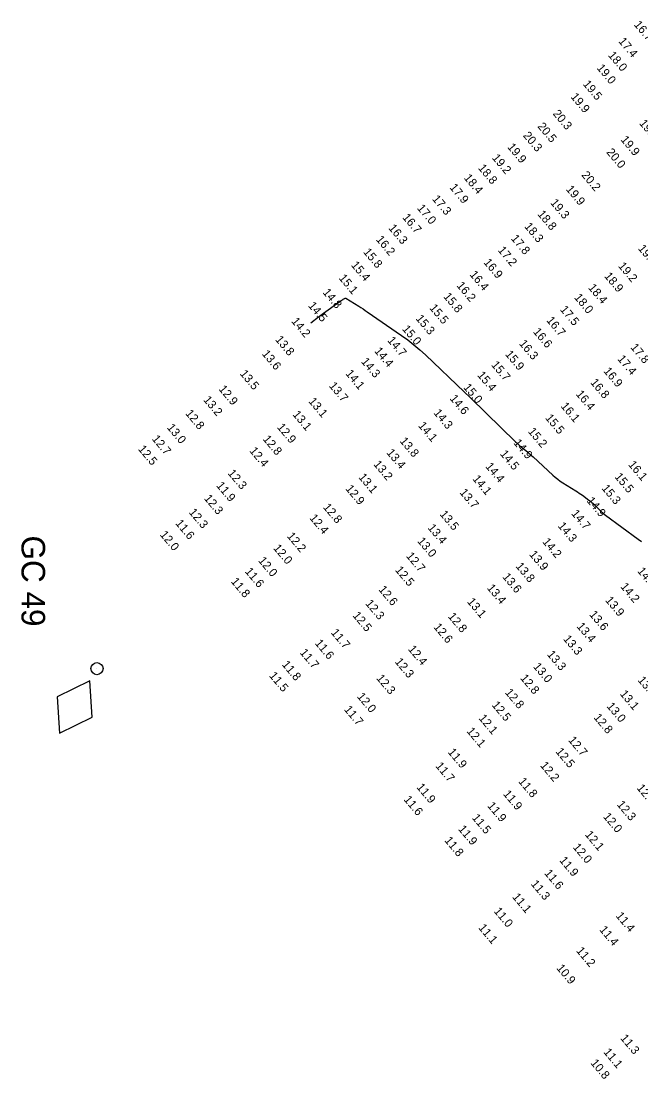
# Model space of a CAD drawing. Extents: x 988130 to 1132882, y 654656 to 841453.
# Drawn here: x 1077032 to 1077400, y 730015 to 730644 of the extents above; entities that cross this region are included whole.
import ezdxf

# ---------------------------------------------------------------- set-up
doc = ezdxf.new("R2010")
doc.units = 0
for name, color, linetype in [('Default', 7, 'Continuous'), ('V-CHAN-NAID', 7, 'Continuous'), ('V-TOPO-MAJR', 7, 'Continuous'), ('V-TOPO-SOUN', 7, 'Continuous')]:
    doc.layers.add(name, color=color, linetype=linetype)

# ---------------------------------------------------------------- blocks, each defined once
blk = doc.blocks.new('POINT_DISPLAY')
at = {"layer": 'Default'}
blk.add_line((0, 0), (0, 0), dxfattribs=at)

msp = doc.modelspace()

# ---------------------------------------------------------------- linework, layer by layer
at = {"layer": 'V-CHAN-NAID'}
msp.add_lwpolyline([(1077072.64, 730251.98), (1077053.25, 730242.39), (1077054.64, 730220.8), (1077074.03, 730230.39)], close=True, dxfattribs=at)
msp.add_circle((1077076.84, 730259.25), 3.6, dxfattribs=at)
at = {"layer": 'V-TOPO-MAJR'}
msp.add_lwpolyline([(1077204.05, 730465.04), (1077208.44, 730468.47), (1077209.18, 730469.03), (1077209.92, 730469.59), (1077210.67, 730470.14), (1077211.42, 730470.68), (1077220.66, 730477.21), (1077220.82, 730477.32), (1077220.97, 730477.43), (1077221.13, 730477.55), (1077221.28, 730477.67), (1077222.01, 730478.23), (1077222.11, 730478.3), (1077222.21, 730478.37), (1077222.31, 730478.43), (1077222.42, 730478.49), (1077222.85, 730478.7), (1077222.95, 730478.76), (1077223.06, 730478.82), (1077223.16, 730478.88), (1077223.25, 730478.95), (1077223.7, 730479.29), (1077223.79, 730479.35), (1077223.87, 730479.4), (1077223.96, 730479.44), (1077224.05, 730479.48), (1077224.43, 730479.61), (1077224.52, 730479.64), (1077224.61, 730479.64), (1077224.7, 730479.62), (1077224.78, 730479.58), (1077232.42, 730474.85), (1077233.72, 730474.04), (1077235.01, 730473.21), (1077236.28, 730472.37), (1077237.55, 730471.51), (1077257.87, 730457.48), (1077261.62, 730454.79), (1077265.25, 730451.95), (1077268.77, 730448.96), (1077272.17, 730445.84), (1077295.38, 730423.66), (1077298.6, 730420.57), (1077301.81, 730417.47), (1077305.01, 730414.36), (1077308.21, 730411.25), (1077325.7, 730394.14), (1077326.53, 730393.34), (1077327.38, 730392.57), (1077328.25, 730391.81), (1077329.14, 730391.08), (1077332.74, 730388.18), (1077333.63, 730387.45), (1077334.51, 730386.7), (1077335.37, 730385.94), (1077336.22, 730385.16), (1077347.81, 730374.33), (1077349.23, 730373.07), (1077350.7, 730371.88), (1077352.24, 730370.77), (1077353.83, 730369.74), (1077361.57, 730364.98), (1077362.56, 730364.36), (1077363.53, 730363.72), (1077364.49, 730363.06), (1077365.44, 730362.38), (1077369.28, 730359.55), (1077370.17, 730358.87), (1077371.03, 730358.16), (1077371.86, 730357.41), (1077372.66, 730356.64), (1077375.82, 730353.46), (1077376.63, 730352.68), (1077377.46, 730351.94), (1077378.32, 730351.23), (1077379.21, 730350.55), (1077398.56, 730336.32), (1077400.62, 730334.8)], dxfattribs=at)

# ---------------------------------------------------------------- block references
at = {"layer": 'V-CHAN-NAID', "xscale": 0.32808398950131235, "yscale": 0.32808398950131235}
msp.add_blockref('POINT_DISPLAY', (1077076.84, 730259.25), dxfattribs=at)

# ---------------------------------------------------------------- texts
at = {"layer": 'V-CHAN-NAID'}
msp.add_text('GC 49', height=14, rotation=270, dxfattribs=at).set_placement((1077031.99, 730338.43))
at = {"layer": 'V-TOPO-SOUN'}
for s, p in [('16.7 ', (1077395.73, 730642.25)), ('17.4 ', (1077386.53, 730632.33)), ('18.0 ', (1077380.38, 730624.04)), ('19.0 ', (1077373.68, 730616.45)), ('19.5 ', (1077365.42, 730606.89)), ('19.9 ', (1077358.11, 730599.32)), ('20.3 ', (1077347.53, 730589.3)), ('20.5 ', (1077338.44, 730581.71)), ('19.9 ', (1077398.9, 730583.55)), ('20.3 ', (1077329.86, 730576.24)), ('19.9 ', (1077387.85, 730573.81)), ('19.9 ', (1077320.5, 730569.4)), ('19.2 ', (1077311.41, 730562.98)), ('20.0 ', (1077379.39, 730566.32)), ('18.8 ', (1077303.13, 730556.91)), ('18.4 ', (1077294.66, 730551.07)), ('20.2 ', (1077364.55, 730552.77)), ('17.9 ', (1077286.15, 730545.37)), ('19.9 ', (1077355.33, 730544.31)), ('17.3 ', (1077275.82, 730538.53)), ('19.3 ', (1077346.06, 730536.27)), ('17.0 ', (1077266.85, 730533.05)), ('16.7 ', (1077258.1, 730527.56)), ('18.8 ', (1077338.41, 730529.49)), ('16.3 ', (1077249.83, 730521.2)), ('18.3 ', (1077330.61, 730522.19)), ('16.2 ', (1077242.4, 730514.43)), ('17.8 ', (1077322.61, 730515.03)), ('15.8 ', (1077234.85, 730506.97)), ('17.2 ', (1077314.85, 730508.06)), ('19.3 ', (1077398.2, 730509.07)), ('15.4 ', (1077227.61, 730499.18)), ('16.9 ', (1077306.38, 730500.79)), ('19.2 ', (1077386.39, 730498.64)), ('16.4 ', (1077298.08, 730493.55)), ('18.9 ', (1077378.09, 730492.62)), ('15.1 ', (1077220.3, 730491.46)), ('16.2 ', (1077290.34, 730487)), ('18.4 ', (1077368.58, 730485.74)), ('14.8 ', (1077210.74, 730482.94)), ('15.8 ', (1077282.51, 730480.47)), ('18.0 ', (1077360.21, 730479.92)), ('14.5 ', (1077202.11, 730475.04)), ('15.5 ', (1077274.17, 730473.71)), ('15.3 ', (1077266.03, 730467.38)), ('17.5 ', (1077351.84, 730472.76)), ('14.2 ', (1077192.1, 730465.77)), ('15.0 ', (1077257.98, 730461.17)), ('16.7 ', (1077343.71, 730466.31)), ('13.8 ', (1077182.51, 730454.88)), ('14.7 ', (1077249.21, 730454.36)), ('16.6 ', (1077335.8, 730459.51)), ('14.4 ', (1077241.43, 730448.05)), ('16.3 ', (1077327.48, 730452.5)), ('17.8 ', (1077393.68, 730450.26)), ('13.6 ', (1077174.61, 730446.37)), ('14.3 ', (1077233.57, 730441.81)), ('15.9 ', (1077319.18, 730446.16)), ('17.4 ', (1077385.94, 730443.36)), ('15.7 ', (1077310.91, 730439.82)), ('16.9 ', (1077377.68, 730436.13)), ('13.5 ', (1077161.53, 730434.58)), ('14.1 ', (1077224.28, 730434.67)), ('15.4 ', (1077302.63, 730433.69)), ('16.8 ', (1077369.84, 730429.37)), ('12.9 ', (1077148.93, 730425.43)), ('13.7 ', (1077214.49, 730427.34)), ('15.0 ', (1077294.33, 730426.43)), ('13.2 ', (1077139.78, 730419.03)), ('13.1 ', (1077202.3, 730418.14)), ('14.6 ', (1077286.26, 730419.83)), ('16.4 ', (1077361.22, 730422.42)), ('12.8 ', (1077129.1, 730410.94)), ('13.1 ', (1077192.85, 730410.3)), ('14.3 ', (1077276.67, 730411.25)), ('16.1 ', (1077352.25, 730415.28)), ('14.1 ', (1077267.52, 730403.66)), ('15.5 ', (1077343.04, 730408.24)), ('13.0 ', (1077118.16, 730402.5)), ('12.9 ', (1077183.6, 730402.74)), ('15.2 ', (1077332.8, 730400.2)), ('12.7 ', (1077109.22, 730395.78)), ('12.8 ', (1077175.16, 730395.68)), ('13.8 ', (1077256.55, 730394.5)), ('14.9 ', (1077324.15, 730393.41)), ('12.5 ', (1077101.03, 730389.72)), ('12.4 ', (1077167.22, 730388.69)), ('13.4 ', (1077248.68, 730387.57)), ('14.5 ', (1077316.16, 730386.85)), ('13.2 ', (1077240.92, 730380.71)), ('14.4 ', (1077307.46, 730379.4)), ('16.1 ', (1077392.37, 730380.48)), ('12.3 ', (1077154.29, 730375.36)), ('13.1 ', (1077232.01, 730373)), ('15.5 ', (1077384.26, 730373.27)), ('11.9 ', (1077147.5, 730368.01)), ('12.9 ', (1077224.31, 730366.14)), ('14.1 ', (1077299.81, 730371.99)), ('15.3 ', (1077376.55, 730366.4)), ('12.3 ', (1077140.2, 730360.39)), ('13.7 ', (1077292.1, 730363.89)), ('12.8 ', (1077210.95, 730355.14)), ('14.9 ', (1077367.69, 730358.95)), ('12.3 ', (1077131.2, 730352.12)), ('12.4 ', (1077202.9, 730348.74)), ('13.5 ', (1077280.32, 730350.97)), ('14.7 ', (1077358.52, 730351.37)), ('11.6 ', (1077123.17, 730345.57)), ('13.4 ', (1077273.17, 730342.87)), ('14.3 ', (1077350.52, 730344)), ('12.0 ', (1077113.99, 730338.81)), ('12.2 ', (1077189.48, 730337.95)), ('13.0 ', (1077267, 730334.96)), ('14.2 ', (1077341.35, 730334.56)), ('12.0 ', (1077181.34, 730330.81)), ('12.0 ', (1077172.43, 730323.37)), ('12.7 ', (1077260.32, 730326.1)), ('13.9 ', (1077333.51, 730327.08)), ('11.6 ', (1077164.51, 730316.94)), ('12.5 ', (1077253.8, 730317.76)), ('13.8 ', (1077325.46, 730320.01)), ('14.5 ', (1077397.77, 730317.13)), ('11.8 ', (1077156.18, 730310.95)), ('13.6 ', (1077317.59, 730313.71)), ('12.6 ', (1077243.92, 730306.17)), ('13.4 ', (1077308.39, 730307.08)), ('14.2 ', (1077387.73, 730307.9)), ('12.3 ', (1077236.1, 730297.85)), ('13.1 ', (1077296.61, 730298.88)), ('13.9 ', (1077378.69, 730299.78)), ('12.5 ', (1077228.54, 730290.71)), ('13.6 ', (1077369.2, 730291.32)), ('12.8 ', (1077285.19, 730290.15)), ('13.4 ', (1077361.7, 730284.27)), ('11.7 ', (1077215.64, 730280.51)), ('12.6 ', (1077276.66, 730283.83)), ('11.6 ', (1077206.09, 730274.24)), ('13.3 ', (1077353.72, 730276.76)), ('11.7 ', (1077197.13, 730268.66)), ('12.4 ', (1077261.5, 730270.69)), ('13.3 ', (1077344.08, 730267.58)), ('11.8 ', (1077186.49, 730261.54)), ('12.3 ', (1077253.62, 730263.18)), ('13.0 ', (1077335.86, 730260.32)), ('11.5 ', (1077178.91, 730254.91)), ('12.3 ', (1077242.63, 730253.41)), ('12.8 ', (1077328.16, 730253.48)), ('13.5 ', (1077398.01, 730252.24)), ('12.0 ', (1077231.16, 730242.51)), ('12.8 ', (1077319.1, 730244.9)), ('13.1 ', (1077387.42, 730244.06)), ('11.7 ', (1077223.45, 730234.81)), ('12.5 ', (1077311.26, 730237.45)), ('13.0 ', (1077379.54, 730236.74)), ('12.1 ', (1077303.45, 730229.63)), ('12.8 ', (1077371.82, 730230.04)), ('12.1 ', (1077296.31, 730221.9)), ('12.7 ', (1077356.72, 730216.55)), ('11.9 ', (1077285.13, 730209.42)), ('12.5 ', (1077349.2, 730209.72)), ('11.7 ', (1077277.78, 730201.2)), ('12.2 ', (1077340.01, 730201.49)), ('11.8 ', (1077327.06, 730191.99)), ('11.9 ', (1077266.51, 730188.57)), ('11.9 ', (1077318, 730184.54)), ('12.4 ', (1077397.41, 730188.08)), ('11.6 ', (1077258.92, 730181.25)), ('11.9 ', (1077308.6, 730177.51)), ('12.3 ', (1077385.59, 730178.27)), ('12.0 ', (1077377.44, 730171.09)), ('11.5 ', (1077299.46, 730170.39)), ('11.9 ', (1077291.3, 730163.66)), ('12.1 ', (1077366.65, 730160.34)), ('11.8 ', (1077283.13, 730156.89)), ('12.0 ', (1077359.45, 730152.87)), ('11.9 ', (1077351.42, 730145.05)), ('11.6 ', (1077342.49, 730137.38)), ('11.3 ', (1077334.49, 730131.01)), ('11.1 ', (1077323.45, 730123.26)), ('11.0 ', (1077312.46, 730114.81)), ('11.4 ', (1077384.96, 730112.03)), ('11.1 ', (1077303.32, 730104.92)), ('11.4 ', (1077375.22, 730103.79)), ('11.2 ', (1077361.44, 730091.25)), ('10.9 ', (1077349.7, 730080.93)), ('11.3 ', (1077387.65, 730039.27)), ('11.1 ', (1077377.65, 730030.99)), ('10.8 ', (1077369.97, 730024.49))]:
    msp.add_text(s, height=5, rotation=310, dxfattribs=at).set_placement(p)

doc.saveas('drawing.dxf')
